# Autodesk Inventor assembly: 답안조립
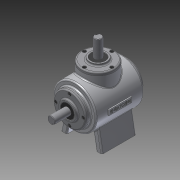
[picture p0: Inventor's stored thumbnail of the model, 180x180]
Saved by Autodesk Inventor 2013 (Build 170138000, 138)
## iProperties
Created: 2015-01
Part Number: 답안조립
Document SubType Name: Assembly
Designer: Administrator
Author: Administrator
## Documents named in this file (15)
- C:\Users\Administrator\Desktop\450106V1027\답안조립.iam
- C:\Users\Administrator\Desktop\450106V1027\본체.ipt
- C:\Users\Administrator\Desktop\450106V1027\M4.ipt
- C:\Users\Administrator\Desktop\450106V1027\메인 베벨기어.ipt
- C:\Users\Administrator\Desktop\450106V1027\메인 축.ipt
- 메인 축.ipt
- C:\Users\Administrator\Desktop\450106V1027\베어링 6203.ipt
- C:\Users\Administrator\Desktop\450106V1027\서브 베벨기어.ipt
- C:\Users\Administrator\Desktop\450106V1027\서브 축.ipt
- 서브 축.ipt
- C:\Users\Administrator\Desktop\450106V1027\오일실.ipt
- C:\Users\Administrator\Desktop\450106V1027\커버.ipt
- C:\Users\Administrator\Desktop\450106V1027\커버2.ipt
- C:\Users\Administrator\Desktop\450106V1027\키 4x4.ipt
- C:\Users\Administrator\Desktop\450106V1027\키 5x5.ipt
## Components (12 placed, 1 different names)
1. M4:2
2. M4:4
3. M4:5
4. M4:6
5. M4:1
6. M4:7
7. M4:8
8. M4:9
9. M4:3
10. M4:10
11. M4:11
12. M4:12
